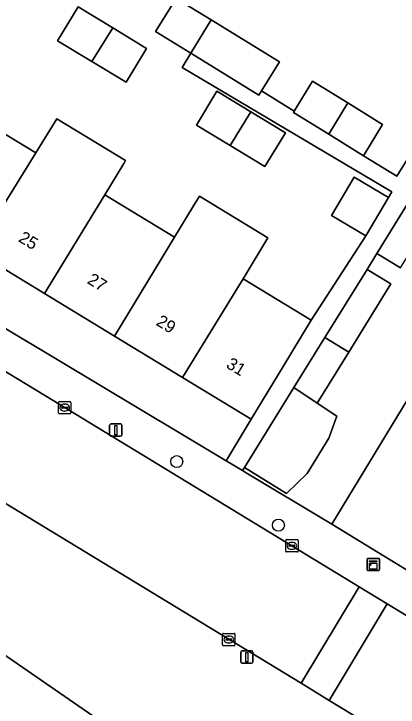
# Model space of a CAD drawing. Extents: x 158352 to 159489, y 383828 to 384603.
# Drawn here: x 158847.1 to 158878.3, y 383907.3 to 383963.7 of the extents above; entities that cross this region are included whole.
import ezdxf

# ---------------------------------------------------------------- set-up
doc = ezdxf.new("R2010")
doc.units = 0
for name, color, linetype in [('IMGEO_Boom', 7, 'Continuous'), ('IMGEO_Erf', 7, 'Continuous'), ('IMGEO_Groenvoorziening', 7, 'Continuous'), ('IMGEO_Kast', 7, 'Continuous'), ('IMGEO_Kolk', 7, 'Continuous'), ('IMGEO_Lichtmast', 7, 'Continuous'), ('IMGEO_Muur', 7, 'Continuous'), ('IMGEO_Pand', 7, 'Continuous'), ('IMGEO_Pand_nummerreeks', 7, 'Continuous'), ('IMGEO_Rijbaan_lokaal_open', 7, 'Continuous'), ('IMGEO_Voetpad_open', 7, 'Continuous')]:
    doc.layers.add(name, color=color, linetype=linetype)

msp = doc.modelspace()

# ---------------------------------------------------------------- linework, layer by layer
at = {"layer": 'IMGEO_Boom'}
for centre in [(158860.326, 383927.298), (158868.582, 383922.131)]:
    msp.add_circle(centre, 0.489, dxfattribs=at)
at = {"layer": 'IMGEO_Erf'}
for points in [[(158849.585, 383940.963), (158843.929, 383944.401), (158838.53, 383947.683), (158832.926, 383951.089), (158827.264, 383954.531), (158821.699, 383957.914), (158816.018, 383961.367), (158817.576, 383963.931), (158814.431, 383965.842), (158814.158, 383966.008), (158811.467, 383961.443)], [(158843.416, 383955.721), (158848.864, 383952.409), (158850.57, 383955.177), (158856.16, 383951.78), (158856.02, 383951.549), (158854.471, 383949.001), (158860.146, 383945.551), (158861.695, 383948.099), (158862.171, 383948.883), (158867.736, 383945.5), (158865.711, 383942.168), (158871.25, 383938.801), (158875.675, 383945.664), (158872.895, 383947.314), (158874.75, 383950.437), (158877.529, 383948.786), (158877.792, 383949.228), (158860.758, 383959.344), (158861.465, 383960.508), (158858.589, 383962.284), (158860.267, 383965.002), (158863.124, 383963.238), (158868.672, 383959.813), (158867.221, 383957.441), (158869.853, 383955.788), (158871.36, 383958.23), (158874.217, 383956.466), (158877.049, 383954.718), (158875.497, 383952.181), (158878.213, 383950.504), (158879.765, 383953.041)], [(158811.894, 383959.106), (158832.465, 383946.483), (158864.328, 383927.368), (158866.364, 383930.763), (158860.79, 383934.151), (158855.261, 383937.512), (158849.585, 383940.963)], [(158878.504, 383943.053), (158876.583, 383944.22), (158875.786, 383942.931), (158877.711, 383941.762), (158874.301, 383936.21), (158871.744, 383932.047), (158873.335, 383930.987), (158872.679, 383929.198), (158870.908, 383926.334), (158869.25, 383924.717), (158865.831, 383926.832), (158865.658, 383926.571), (158865.759, 383926.51), (158865.975, 383926.38), (158872.913, 383922.218), (158879.501, 383933.053)]]:
    msp.add_lwpolyline(points, dxfattribs=at)
for points in [[(158855.126, 383962.571), (158857.879, 383960.898), (158856.208, 383958.149), (158853.438, 383959.832), (158850.641, 383961.532), (158852.312, 383964.281)], [(158866.344, 383955.752), (158869.161, 383954.04), (158867.49, 383951.291), (158864.674, 383953.002), (158861.923, 383954.674), (158863.594, 383957.423)]]:
    msp.add_lwpolyline(points, close=True, dxfattribs=at)
at = {"layer": 'IMGEO_Groenvoorziening'}
for points in [[(158872.704, 383907.882), (158870.424, 383909.269), (158823.283, 383937.959)], [(158815.357, 383932.963), (158859.991, 383902.143)], [(158879.355, 383898.226), (158878.096, 383899.685), (158876.749, 383901.064), (158875.318, 383902.355), (158873.81, 383903.555), (158873.673, 383903.657), (158872.578, 383904.354), (158871.622, 383904.678), (158870.62, 383904.797), (158869.615, 383904.704), (158859.991, 383902.143), (158815.357, 383932.963), (158842.289, 383911.153)], [(158876.427, 383905.616), (158872.704, 383907.882)]]:
    msp.add_lwpolyline(points, dxfattribs=at)
at = {"layer": 'IMGEO_Kast'}
for p, q in [((158875.8, 383918.508), (158875.8, 383919.349)), ((158875.8, 383919.349), (158875.8, 383918.508)), ((158875.875, 383919.433), (158876.716, 383919.433)), ((158876.716, 383919.433), (158875.875, 383919.433)), ((158876.8, 383919.358), (158876.8, 383918.517)), ((158876.8, 383918.517), (158876.8, 383919.358)), ((158876.725, 383918.433), (158875.884, 383918.433)), ((158875.884, 383918.433), (158876.725, 383918.433))]:
    msp.add_line(p, q, dxfattribs=at)
for points in [[(158875.995, 383919.223), (158876.595, 383919.223), (158876.595, 383919.138), (158875.995, 383919.138), (158875.995, 383919.223)], [(158875.995, 383919.048), (158876.595, 383919.048), (158876.595, 383918.559), (158875.995, 383918.559), (158875.995, 383919.048)]]:
    msp.add_lwpolyline(points, dxfattribs=at)
msp.add_circle((158876.079, 383918.897), 0.0377, dxfattribs=at)
for centre, start, end in [((158875.878, 383919.355), 92.4484, 184.2845), ((158875.878, 383919.355), 92.4484, 184.2845), ((158876.722, 383919.355), 2.4484, 94.2845), ((158876.722, 383919.355), 2.4484, 94.2845), ((158875.878, 383918.511), 182.4484, 274.2845), ((158875.878, 383918.511), 182.4484, 274.2845), ((158876.722, 383918.511), 272.4484, 4.2845), ((158876.722, 383918.511), 272.4484, 4.2845)]:
    msp.add_arc(centre, 0.0779, start, end, dxfattribs=at)
at = {"layer": 'IMGEO_Kolk'}
for p, q in [((158850.72, 383931.264), (158850.72, 383932.116)), ((158850.795, 383932.19), (158851.647, 383932.19)), ((158851.721, 383932.116), (158851.721, 383931.264)), ((158850.979, 383931.684), (158850.979, 383931.696)), ((158851.417, 383931.647), (158851.019, 383931.647)), ((158851.022, 383931.733), (158851.42, 383931.733)), ((158851.208, 383931.97), (158851.233, 383931.97)), ((158851.463, 383931.696), (158851.463, 383931.684)), ((158851.647, 383931.19), (158850.795, 383931.19)), ((158851.231, 383931.41), (158851.206, 383931.41)), ((158869.178, 383920.027), (158869.178, 383920.879)), ((158869.253, 383920.953), (158870.105, 383920.953)), ((158869.666, 383920.733), (158869.691, 383920.733)), ((158870.179, 383920.879), (158870.179, 383920.027)), ((158869.437, 383920.447), (158869.437, 383920.459)), ((158869.875, 383920.41), (158869.477, 383920.41)), ((158869.48, 383920.496), (158869.878, 383920.496)), ((158869.689, 383920.173), (158869.664, 383920.173)), ((158869.921, 383920.459), (158869.921, 383920.447)), ((158870.105, 383919.953), (158869.253, 383919.953)), ((158864.054, 383912.404), (158864.054, 383913.256)), ((158864.129, 383913.33), (158864.981, 383913.33)), ((158864.313, 383912.824), (158864.313, 383912.836)), ((158864.356, 383912.873), (158864.754, 383912.873)), ((158864.542, 383913.11), (158864.567, 383913.11)), ((158864.797, 383912.836), (158864.797, 383912.824)), ((158865.055, 383913.256), (158865.055, 383912.404)), ((158864.981, 383912.33), (158864.129, 383912.33)), ((158864.751, 383912.787), (158864.353, 383912.787)), ((158864.565, 383912.55), (158864.54, 383912.55))]:
    msp.add_line(p, q, dxfattribs=at)
for points in [[(158850.72, 383931.264), (158850.72, 383932.116)], [(158850.795, 383932.19), (158851.647, 383932.19)], [(158851.721, 383932.116), (158851.721, 383931.264)], [(158851.647, 383931.19), (158850.795, 383931.19)], [(158869.178, 383920.027), (158869.178, 383920.879)], [(158869.253, 383920.953), (158870.105, 383920.953)], [(158870.179, 383920.879), (158870.179, 383920.027)], [(158870.105, 383919.953), (158869.253, 383919.953)], [(158864.054, 383912.404), (158864.054, 383913.256)], [(158864.129, 383913.33), (158864.981, 383913.33)], [(158865.055, 383913.256), (158865.055, 383912.404)], [(158864.981, 383912.33), (158864.129, 383912.33)]]:
    msp.add_lwpolyline(points, dxfattribs=at)
for centre, radius, start, end in [((158850.797, 383932.114), 0.0765, 91.552, 178.448), ((158850.797, 383932.114), 0.0765, 91.552, 178.448), ((158851.645, 383932.114), 0.0765, 1.552, 88.448), ((158851.645, 383932.114), 0.0765, 1.552, 88.448), ((158851.019, 383931.693), 0.0403, 85.8775, 175.7526), ((158851.016, 383931.683), 0.0366, 178.938, 274.7102), ((158851.42, 383931.69), 0.043, 264.8664, 352.4533), ((158851.424, 383931.695), 0.0386, 1.7309, 96.639), ((158850.797, 383931.266), 0.0765, 181.552, 268.448), ((158850.797, 383931.266), 0.0765, 181.552, 268.448), ((158851.645, 383931.266), 0.0765, 271.552, 358.448), ((158851.645, 383931.266), 0.0765, 271.552, 358.448), ((158869.255, 383920.877), 0.0765, 91.552, 178.448), ((158869.255, 383920.877), 0.0765, 91.552, 178.448), ((158870.103, 383920.877), 0.0765, 1.552, 88.448), ((158870.103, 383920.877), 0.0765, 1.552, 88.448), ((158869.477, 383920.456), 0.0403, 85.8775, 175.7526), ((158869.474, 383920.446), 0.0366, 178.938, 274.7102), ((158869.878, 383920.453), 0.043, 264.8664, 352.4533), ((158869.882, 383920.458), 0.0386, 1.7309, 96.639), ((158869.255, 383920.029), 0.0765, 181.552, 268.448), ((158869.255, 383920.029), 0.0765, 181.552, 268.448), ((158870.103, 383920.029), 0.0765, 271.552, 358.448), ((158870.103, 383920.029), 0.0765, 271.552, 358.448), ((158864.131, 383913.254), 0.0765, 91.552, 178.448), ((158864.131, 383913.254), 0.0765, 91.552, 178.448), ((158864.353, 383912.833), 0.0403, 85.8775, 175.7526), ((158864.35, 383912.823), 0.0366, 178.938, 274.7102), ((158864.754, 383912.83), 0.043, 264.8664, 352.4533), ((158864.758, 383912.835), 0.0386, 1.7309, 96.639), ((158864.979, 383913.254), 0.0765, 1.552, 88.448), ((158864.979, 383913.254), 0.0765, 1.552, 88.448), ((158864.131, 383912.406), 0.0765, 181.552, 268.448), ((158864.131, 383912.406), 0.0765, 181.552, 268.448), ((158864.979, 383912.406), 0.0765, 271.552, 358.448), ((158864.979, 383912.406), 0.0765, 271.552, 358.448)]:
    msp.add_arc(centre, radius, start, end, dxfattribs=at)
for centre, major_axis, ratio, start_param, end_param in [((158851.207, 383931.69), (-0.387, 0.002), 0.722429, 4.712389, 7.853982), ((158851.232, 383931.69), (-0.39, 0.002), 0.717154, 1.570796, 4.712389), ((158869.665, 383920.453), (-0.387, 0.002), 0.722429, 4.712389, 7.853982), ((158869.69, 383920.453), (-0.39, 0.002), 0.717154, 1.570796, 4.712389), ((158864.541, 383912.83), (-0.387, 0.002), 0.722429, 4.712389, 7.853982), ((158864.566, 383912.83), (-0.39, 0.002), 0.717154, 1.570796, 4.712389)]:
    msp.add_ellipse(centre, major_axis=major_axis, ratio=ratio, start_param=start_param, end_param=end_param, dxfattribs=at)
at = {"layer": 'IMGEO_Lichtmast'}
for p, q in [((158854.974, 383930.359), (158855.764, 383930.359)), ((158855.764, 383930.359), (158854.974, 383930.359)), ((158854.874, 383929.459), (158854.874, 383930.259)), ((158854.874, 383930.259), (158854.874, 383929.459)), ((158855.864, 383930.259), (158855.864, 383929.459)), ((158855.864, 383929.459), (158855.864, 383930.259)), ((158855.764, 383929.359), (158854.974, 383929.359)), ((158854.974, 383929.359), (158855.764, 383929.359)), ((158865.522, 383910.999), (158865.522, 383911.799)), ((158865.522, 383911.799), (158865.522, 383910.999)), ((158865.622, 383911.899), (158866.412, 383911.899)), ((158866.412, 383911.899), (158865.622, 383911.899)), ((158866.512, 383911.799), (158866.512, 383910.999)), ((158866.512, 383910.999), (158866.512, 383911.799)), ((158866.412, 383910.899), (158865.622, 383910.899)), ((158865.622, 383910.899), (158866.412, 383910.899))]:
    msp.add_line(p, q, dxfattribs=at)
for points in [[(158855.294, 383930.234), (158855.444, 383930.234), (158855.444, 383929.484), (158855.294, 383929.484), (158855.294, 383930.234)], [(158865.942, 383911.774), (158866.092, 383911.774), (158866.092, 383911.024), (158865.942, 383911.024), (158865.942, 383911.774)]]:
    msp.add_lwpolyline(points, dxfattribs=at)
for centre, start, end in [((158854.974, 383930.259), 90, 180), ((158854.974, 383930.259), 90, 180), ((158855.764, 383930.259), 0, 90), ((158855.764, 383930.259), 360, 90), ((158854.974, 383929.459), 180, 270), ((158854.974, 383929.459), 180, 270), ((158855.764, 383929.459), 270, 0), ((158855.764, 383929.459), 270, 0), ((158865.622, 383911.799), 90, 180), ((158865.622, 383911.799), 90, 180), ((158866.412, 383911.799), 0, 90), ((158866.412, 383911.799), 360, 90), ((158865.622, 383910.999), 180, 270), ((158865.622, 383910.999), 180, 270), ((158866.412, 383910.999), 270, 0), ((158866.412, 383910.999), 270, 0)]:
    msp.add_arc(centre, 0.1, start, end, dxfattribs=at)
at = {"layer": 'IMGEO_Muur'}
msp.add_lwpolyline([(158865.975, 383926.38), (158872.913, 383922.218)], dxfattribs=at)
at = {"layer": 'IMGEO_Pand'}
for points in [[(158861.465, 383960.508), (158863.124, 383963.238), (158860.267, 383965.002), (158858.589, 383962.284)], [(158853.438, 383959.832), (158855.126, 383962.571), (158852.312, 383964.281), (158850.641, 383961.532)], [(158863.124, 383963.238), (158861.465, 383960.508), (158867.005, 383957.088), (158867.221, 383957.441), (158868.672, 383959.813)], [(158853.438, 383959.832), (158856.208, 383958.149), (158857.879, 383960.898), (158855.126, 383962.571)], [(158874.217, 383956.466), (158871.36, 383958.23), (158869.853, 383955.788), (158869.798, 383955.699), (158872.673, 383953.925)], [(158864.674, 383953.002), (158866.344, 383955.752), (158863.594, 383957.423), (158861.923, 383954.674)], [(158874.217, 383956.466), (158872.673, 383953.925), (158875.497, 383952.181), (158877.049, 383954.718)], [(158843.416, 383955.721), (158838.53, 383947.683), (158843.929, 383944.401), (158848.864, 383952.409)], [(158864.674, 383953.002), (158867.49, 383951.291), (158869.161, 383954.04), (158866.344, 383955.752)], [(158854.471, 383949.001), (158856.02, 383951.549), (158856.16, 383951.78), (158850.57, 383955.177), (158848.864, 383952.409), (158843.929, 383944.401), (158849.585, 383940.963)], [(158877.529, 383948.786), (158874.75, 383950.437), (158872.895, 383947.314), (158875.675, 383945.664)], [(158860.146, 383945.551), (158854.471, 383949.001), (158849.585, 383940.963), (158855.261, 383937.512)], [(158865.711, 383942.168), (158867.736, 383945.5), (158862.171, 383948.883), (158861.695, 383948.099), (158860.146, 383945.551), (158855.261, 383937.512), (158860.79, 383934.151)], [(158881.126, 383947.323), (158879.217, 383948.481), (158876.583, 383944.22), (158878.504, 383943.053)], [(158875.786, 383942.931), (158872.36, 383937.388), (158874.301, 383936.21), (158877.711, 383941.762)], [(158865.711, 383942.168), (158860.79, 383934.151), (158866.364, 383930.763), (158868.962, 383935.036), (158871.25, 383938.801)], [(158872.36, 383937.388), (158869.841, 383933.315), (158871.744, 383932.047), (158874.301, 383936.21)], [(158873.335, 383930.987), (158871.744, 383932.047), (158869.841, 383933.315), (158865.831, 383926.832), (158869.25, 383924.717), (158870.908, 383926.334), (158872.679, 383929.198)], [(158879.501, 383933.053), (158872.913, 383922.218), (158880.931, 383917.315), (158887.551, 383928.166)]]:
    msp.add_lwpolyline(points, close=True, dxfattribs=at)
at = {"layer": 'IMGEO_Rijbaan_lokaal_open'}
for points in [[(158823.283, 383937.959), (158870.424, 383909.269), (158875.147, 383917.123), (158849.664, 383932.637), (158828.048, 383945.782)], [(158875.147, 383917.123), (158870.424, 383909.269), (158872.704, 383907.882), (158877.427, 383915.735)]]:
    msp.add_lwpolyline(points, close=True, dxfattribs=at)
msp.add_lwpolyline([(158890.133, 383907.999), (158877.427, 383915.735), (158872.704, 383907.882), (158876.427, 383905.616)], dxfattribs=at)
at = {"layer": 'IMGEO_Voetpad_open'}
for points in [[(158879.765, 383953.041), (158878.213, 383950.504), (158875.497, 383952.181), (158872.673, 383953.925), (158869.798, 383955.699), (158869.853, 383955.788), (158867.221, 383957.441), (158867.005, 383957.088), (158861.465, 383960.508), (158860.758, 383959.344), (158877.792, 383949.228), (158877.529, 383948.786), (158875.675, 383945.664), (158871.25, 383938.801), (158868.962, 383935.036), (158866.364, 383930.763), (158864.328, 383927.368), (158865.658, 383926.571), (158865.831, 383926.832), (158869.841, 383933.315), (158872.36, 383937.388), (158875.786, 383942.931), (158876.583, 383944.22), (158879.217, 383948.481)], [(158811.929, 383955.585), (158825.751, 383947.179), (158828.048, 383945.782), (158849.664, 383932.637), (158875.147, 383917.123), (158877.427, 383915.735), (158890.133, 383907.999)], [(158894.205, 383907.454), (158893.501, 383909.418), (158888.633, 383912.412), (158886.902, 383913.477), (158880.931, 383917.315), (158872.913, 383922.218), (158865.975, 383926.38), (158865.759, 383926.51), (158865.658, 383926.571), (158864.328, 383927.368), (158832.465, 383946.483)]]:
    msp.add_lwpolyline(points, dxfattribs=at)

# ---------------------------------------------------------------- texts
at = {"layer": 'IMGEO_Pand_nummerreeks'}
for s, rotation, p in [('25', 328.705, (158847.387, 383945.248)), ('27', 328.705, (158852.981, 383941.847)), ('29', 328.705, (158858.575, 383938.447)), ('31', 328.7057, (158864.266, 383934.987))]:
    msp.add_text(s, height=1, rotation=rotation, dxfattribs=at).set_placement(p)

doc.saveas('drawing.dxf')
